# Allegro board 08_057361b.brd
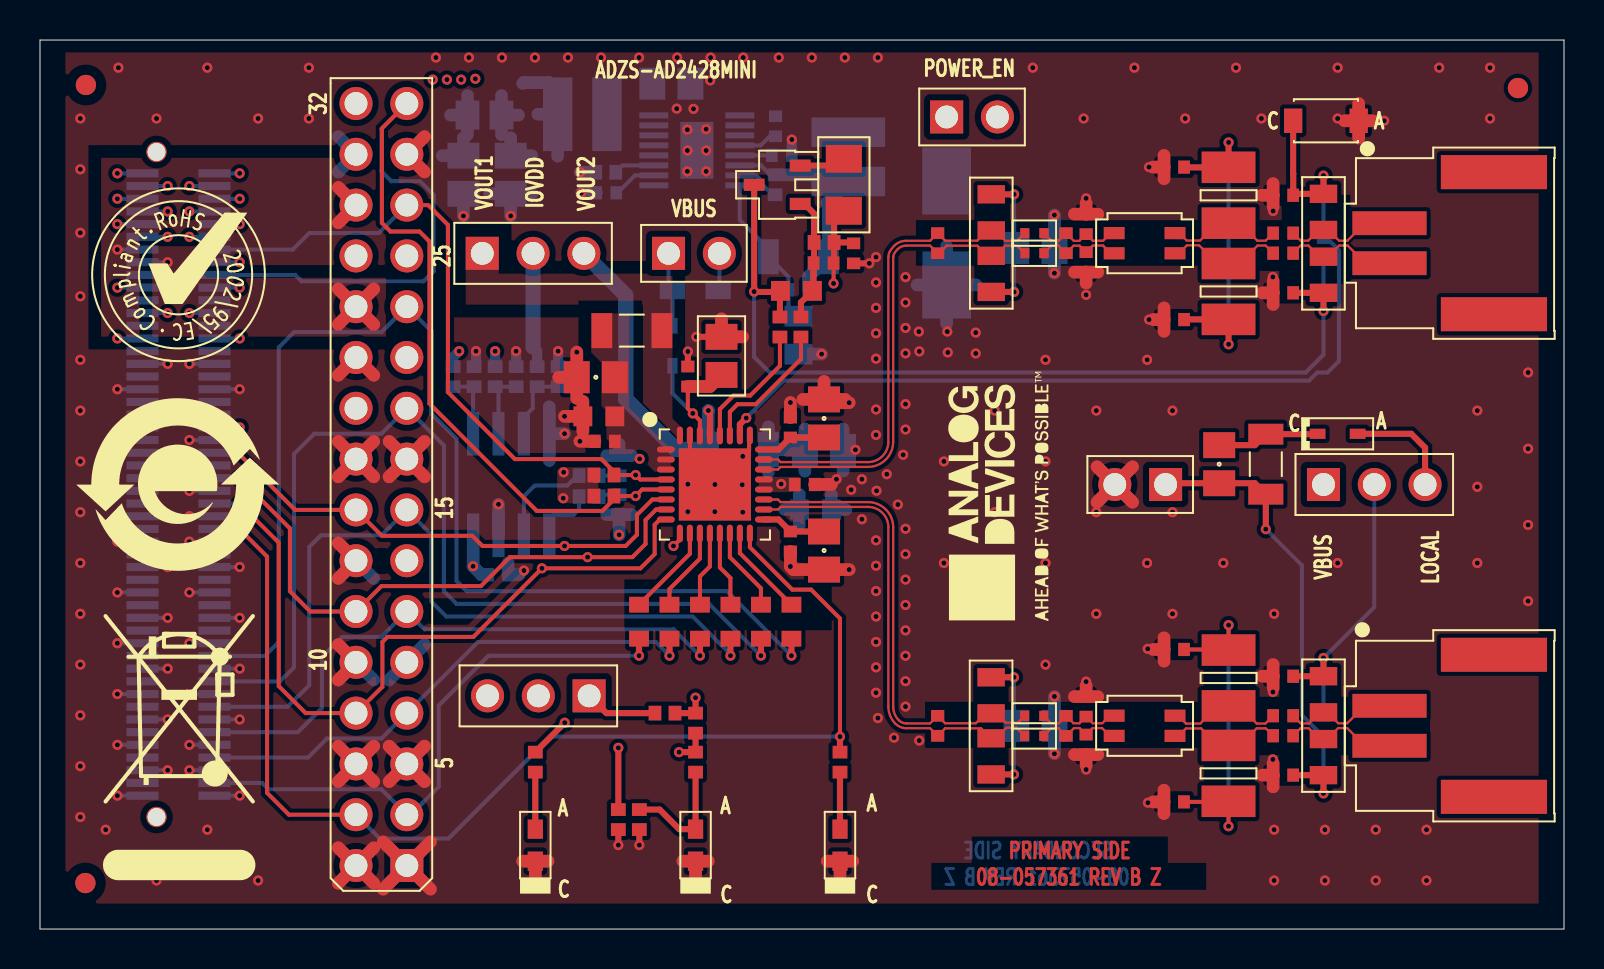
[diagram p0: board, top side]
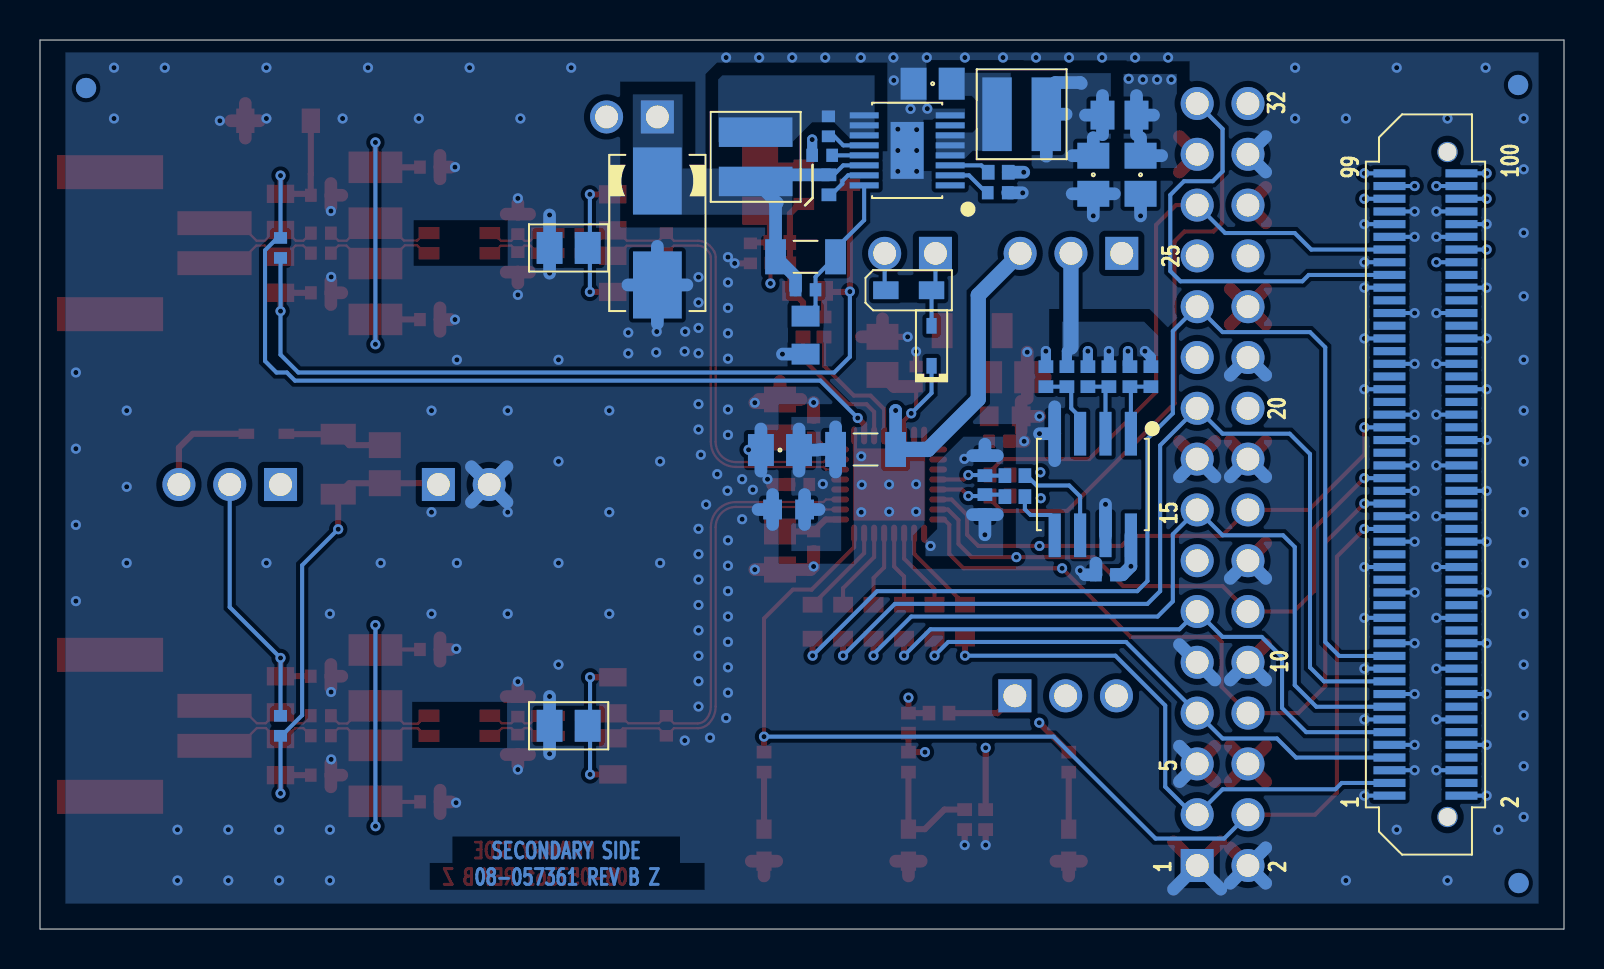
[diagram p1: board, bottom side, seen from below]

Outline 76.2 x 44.45 mm; copper layers: TOP, L2_GND, L3_PWR, BOTTOM. Coordinates in mm from the lower left corner of the outline.
Outline path: 0,44.45 0,0 76.2,0 76.2,44.45 0,44.45

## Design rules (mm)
constraint set DEFAULT: min track width 0.203
net group A: nets AN AP
net group A2: nets UNNAMED_3_CAP_I10_N2 UNNAMED_3_CAP_I12_N2
net group A3: nets UNNAMED_3_CAP_I20_N1 UNNAMED_3_CAP_I22_N1
net group A4: nets UNNAMED_3_CAP_I20_N2 UNNAMED_3_CAP_I22_N2
net group B: nets BN BP

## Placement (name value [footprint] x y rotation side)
C1  4.7UF  [C0805H60]  27.79 27.59 0 top
C2  0.1UF  [C0402]  28.24 24.38 0 top
C3  4700PF  [C0603]  27.94 25.63 0 top
C4  4.7UF  [C0805H60]  39.2 23.95 180 bottom
C5  4700PF  [C0603]  38.77 20.97 180 bottom
C6  0.1UF  [C0402]  32.39 27.62 270 top
C7  0.1UF  [C0402]  37.52 25.07 270 top
C8  0.1UF  [C0402]  37.52 19.38 90 top
C9  0.1UF  [C0402]  38.24 22.23 180 top
C10  10UF  [C0805H53]  34.07 28.66 270 top
C11  4.7UF  [C0805H60]  39.2 25.53 270 top
C12  4.7UF  [C0805H60]  39.2 18.92 90 top
C13  15NF  [C0402]  39.18 33.3 0 top
C14  3300PF  [C0603]  37.82 31.91 180 top
C15  0.033UF  [C0402]  40.68 33.78 90 top
C16  0.33UF  [C0805H53]  49.77 10.16 180 bottom
C17  12PF  [C0402]  44.88 10.16 90 top
C18  27PF  [C0402]  52.31 11.12 90 top
C19  27PF  [C0402]  52.31 9.22 90 top
C20  12PF  [C0402]  51.31 10.16 90 top
C21  0.033UF  [C0402]  56.7 13.98 180 top
C22  0.033UF  [C0402]  56.7 6.36 0 top
C23  0.01UF  [C0402]  62.16 10.66 0 top
C24  0.01UF  [C0402]  62.16 9.66 0 top
C25  0.033UF  [C0402]  62.16 12.64 0 top
C26  0.033UF  [C0402]  62.16 7.69 0 top
C27  0.033UF  [C0402]  64.17 10.16 90 bottom
C28  4.7UF  [C0805H60]  58.96 23.24 90 top
C29  0.33UF  [C0805H53]  49.77 34.05 180 bottom
C30  12PF  [C0402]  44.88 34.29 270 top
C31  27PF  [C0402]  52.31 33.34 270 top
C32  27PF  [C0402]  52.31 35.24 270 top
C33  12PF  [C0402]  51.31 34.29 270 top
C34  0.033UF  [C0402]  56.7 38.09 180 top
C35  0.033UF  [C0402]  56.7 30.47 0 top
C36  0.01UF  [C0402]  62.16 33.79 0 top
C37  0.01UF  [C0402]  62.16 34.79 0 top
C38  0.033UF  [C0402]  62.16 31.81 0 top
C39  0.033UF  [C0402]  62.16 36.69 0 top
C40  0.033UF  [C0402]  64.17 34.05 270 bottom
C41  4.7UF  [C0805H60]  21.17 37.71 90 bottom
C42  4.7UF  [C0805H60]  23.54 37.71 90 bottom
C43  4.7UF  [C0805H60]  31.57 42.27 180 bottom
C44  0.01uF  [C0402]  28.31 36.81 0 bottom
C45  10pF  [C0402]  37.92 31.96 0 bottom
C46  0.1uF  [C0402]  22.9 17.71 0 bottom
C47  0.1uF  [C0402]  36.78 40.13 90 bottom
C48  1uF  [C0402]  37.09 38.68 0 bottom
C49  47UF  [C7343-43]  45.33 34.8 270 bottom
D1  CDBU0130L  [SOD523F]  31.62 29.16 90 bottom
D2  ZLLS400TA  [SOD323]  32.77 31.94 180 bottom
D3  CDBU0130L  [SOD523F]  64.88 24.76 0 top
D4  TPSMF4L28A  [SOD123FL]  64.3 40.41 0 top
DS1  APT1608LVBC/D  [LED0603]  40 4.19 90 top
DS2  APT1608LVBC/D  [LED0603]  24.77 4.19 90 top
DS3  APT1608LVBC/D  [LED0603]  32.78 4.19 90 top
E1  220OHM  [L0805]  22.23 40.69 0 bottom
L1  3.3UH  [L0805H57]  47.55 11.68 270 top
L2  3.3UH  [L0805H57]  47.55 8.63 270 top
L3  180NH  [L0402-3]  49.71 10.66 0 top
L4  180NH  [L0402-3]  49.71 9.66 0 top
L5  100UH  [LSML126W98H98]  55.23 10.16 0 top
L6  3.3UH  [L0805H57]  64.17 11.74 90 top
L7  3.3UH  [L0805H57]  64.17 8.6 90 top
L8  3.3UH  [L0805H57]  47.56 32.76 90 top
L9  3.3UH  [L0805H57]  47.56 35.83 90 top
L10  180NH  [L0402-3]  49.72 33.79 0 top
L11  180NH  [L0402-3]  49.72 34.79 0 top
L12  100UH  [LSML126W98H98]  55.23 34.29 0 top
L13  3.3UH  [L0805H57]  64.17 32.71 270 top
L14  3.3UH  [L0805H57]  64.17 35.85 270 top
L15  4.7uH  [LSMSQ157H83]  27.12 40.74 0 bottom
L16  2.2uH  [LSMSQ157H83]  40.42 38.61 270 bottom
NOREF  -  []  0 44.45 0 top
NOREF#2  -  []  76.2 0 0 top
NOREF#3  -  []  21.18 303 0 top
NOREF#4  -  []  0 44.45 270 top
NOREF#5  -  []  47.95 21.34 90 top
NOREF#6  -  []  -39.78 -67.84 0 top
NOREF#7  -  [unnamed#2]  2.27 2.3 0 top
NOREF#8  -  []  5.83 5.6 0 top
NOREF#9  -  []  16.23 19.33 0 top
NOREF#10  -  []  76.2 44.45 180 top
NOREF#11  -  [unnamed#2]  73.9 42.05 0 top
NOREF#12  -  []  31.12 -36.83 270 top
NOREF#13  -  []  134.54 129.29 0 top
NOREF#14  -  [unnamed#2]  2.29 42.2 0 top
NOREF#15  -  []  -39.78 -67.84 0 top
NOREF#16  -  []  -39.78 -67.84 0 top
NOREF#17  -  []  -1.68 258.55 0 top
NOREF#18  -  []  76.2 0 90 top
NOREF#19  -  []  5.83 5.6 0 top
NOREF#20  -  []  38.54 66.26 0 top
NOREF#21  -  []  0 44.45 0 top
NOREF#22  -  []  6.93 32.71 0 top
NOREF#23  -  []  -29.6 143.68 0 top
NOREF#24  -  []  0 0 0 top
NOREF#25  -  []  0 0 0 top
NOREF#26  -  []  -39.78 -67.84 0 top
NOREF#27  -  []  76.2 0 90 top
NOREF#28  -  []  6.88 22.23 0 top
NOREF#29  -  []  0 0 0 top
NOREF#30  -  [unnamed#2]  2.27 2.3 180 bottom
NOREF#31  -  [unnamed#2]  73.9 42.05 180 bottom
NOREF#32  -  [unnamed#2]  2.29 42.2 180 bottom
P1  LSS-150-01-L-DV-A-K  [CNSAMTECLSS-150-01-X-DV-A]  6.93 22.23 90 bottom
P2  TSW-116-08-G-D  [CNBERG2X16H330LD36]  18.34 3.17 90 top
P3  22-10-2031  [CNHDR1X3H440]  22.11 33.78 0 top
P4  22-10-2031  [CNHDR1X3H440]  27.46 11.66 180 top
P5  3-644456-2  [CNHDR1X2H408]  31.43 33.78 0 top
P6  22-10-2031  [CNHDR1X3H440]  64.17 22.23 0 top
P7  3-644456-2  [CNHDR1X2H408]  56.28 22.23 180 top
P8  3-644456-2  [CNHDR1X2H408]  45.33 40.6 0 top
P9  502352-0200  [CNHDR1X2H260]  70.75 10.16 270 top
P10  502352-0200  [CNHDR1X2H260]  70.75 34.29 270 top
Q1  DMP3098L-7  [SOT23_B]  36.86 37.21 90 top
R1  1.5K  [R0402]  40 8.34 90 top
R2  1.5K  [R0402]  24.77 8.34 90 top
R3  10K  [R0402]  32.78 10.29 90 top
R4  1.5K  [R0402]  32.78 8.34 90 top
R5  10K  [R0402]  29.97 5.47 90 top
R6  33  [R0603]  29.95 15.37 90 top
R7  33  [R0603]  31.47 15.37 90 top
R8  33  [R0603]  33 15.37 90 top
R9  33  [R0603]  34.52 15.37 90 top
R10  33  [R0603]  36.05 15.37 90 top
R11  33  [R0603]  37.57 15.37 90 top
R12  10K  [R0402]  31.25 10.79 0 top
R13  10K  [R0402]  28.92 5.47 90 top
R14  10K  [R0402]  28.2 22.7 180 top
R15  10K  [R0402]  28.2 21.65 180 top
R16  0  [R1206]  29.59 29.92 180 top
R17  0  [R1206]  34.92 23.98 0 bottom
R18  3.3K  [R0402]  38.05 30.1 90 top
R19  1K  [R0402]  37 30.1 90 top
R20  33K  [R0402]  39.2 34.33 0 top
R21  1  [R1206-2]  40.19 37.21 270 top
R22  120  [R1210]  59.43 12.55 270 top
R23  120  [R1210]  59.42 7.78 270 top
R24  4.7K  [R1206]  61.29 23.24 90 top
R25  120  [R1210]  59.43 31.88 90 top
R26  120  [R1210]  59.43 36.69 90 top
R27  10K  [R0402]  20.66 27.62 90 bottom
R28  10K  [R0402]  21.71 27.62 270 bottom
R29  10K  [R0402]  22.76 27.62 90 bottom
R30  10K  [R0402]  23.81 27.62 270 bottom
R31  10K  [R0402]  24.86 27.62 90 bottom
R32  10K  [R0402]  25.91 27.62 270 bottom
R33  18.2K  [R0402]  28.29 37.84 0 bottom
R34  130K  [R0805]  37.92 29.69 90 bottom
R35  1MEG  [R1206]  37.92 33.61 0 bottom
R36  100K  [R0402]  36.75 37.21 270 bottom
R37  0  [R0402]  27.46 21.62 0 bottom
R38  0  [R0402]  27.46 22.67 0 bottom
R39  3.3K  [R0402]  28.96 21.22 270 bottom
R40  3.3K  [R0402]  28.96 23.17 90 bottom
U1  AD2428WCCSZ  [QFN32_5X5_PAD3_6X3_6]  33.74 22.23 270 top
U2  24AA512T-I/SN  [SO8]  23.56 22.23 0 bottom
U3  LT8620EMSE#PBF  [MSOP16_PAD2_845X1_651]  32.84 38.93 90 bottom

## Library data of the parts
C1 C4 C11 C12 = CAP: Tolerance: 10; User Part Number: UPN; alternate symbols: (); part number: CAP_SM-4.7UF,35V,10,E030887,C0805H60; tolerance: 10
C2 C6-C9 = CAP: User Part Number: UPN; Tolerance: 10; alternate symbols: (); part number: CAP_SM-0.1UF,25V,10,E033331,C0402; tolerance: 10
C3 C5 = CAP: User Part Number: UPN; Tolerance: 5; alternate symbols: (); part number: CAP_SM-4700PF,50V,5,E029760,C0603; tolerance: 5
C10 = CAP: Tolerance: 10; User Part Number: UPN; alternate symbols: (C0805SP); part number: CAP_SM-10UF,6.3V,10,E028139,C0805H53; tolerance: 10
C13 = CAP: User Part Number: UPN; Tolerance: 10; alternate symbols: (); part number: CAP_SM-15NF,35V,10,E033385,C0402; tolerance: 10
C14 = CAP: User Part Number: UPN; Tolerance: 10; alternate symbols: (); part number: CAP_SM-3300PF,50V,10,E030855,C0603; tolerance: 10
C15 C21 C22 C25-C27 C34 C35 C38-C40 = CAP: User Part Number: UPN; Tolerance: 10; alternate symbols: (); part number: CAP_SM-0.033UF,25V,10,E025701,C0402; tolerance: 10
C16 C29 = CAP: Tolerance: 10; User Part Number: UPN; alternate symbols: (); part number: CAP_SM-0.33UF,25V,10,E031755,C0805H53; tolerance: 10
C17 C20 C30 C33 = CAP: User Part Number: UPN; Tolerance: 5; alternate symbols: (); part number: CAP_SM-12PF,50V,5,E034633,C0402; tolerance: 5
C18 C19 C31 C32 = CAP: User Part Number: UPN; Tolerance: 5; alternate symbols: (); part number: CAP_SM-27PF,50V,5,E033384,C0402; tolerance: 5
C23 C24 C36 C37 = CAP: User Part Number: UPN; Tolerance: 10; alternate symbols: (); part number: CAP_SM-0.01UF,25V,10,E030894,C0402; tolerance: 10
C28 C41-C43 = CAP: Tolerance: 10; User Part Number: UPN; alternate symbols: (); part number: CAP_SM-4.7UF,35V,10,E026260,C0805H60; tolerance: 10
C44 = CAP: User Part Number: UPN; Tolerance: -20 to 80%; alternate symbols: (); part number: CAP_SM-0.01UF,50V,-20 TO 80%,E012614,C0402; tolerance: -20 to 80%
C45 = CAP: User Part Number: UPN; Tolerance: 5; alternate symbols: (); part number: CAP_SM-10PF,50V,5,E007982,C0402; tolerance: 5
C46 C47 = CAP: User Part Number: UPN; Tolerance: 10; alternate symbols: (); part number: CAP_SM-0.1UF,35V,10,E019488,C0402; tolerance: 10
C48 = CAP: User Part Number: UPN; Tolerance: 20; alternate symbols: (); part number: CAP_SM-1UF,16V,20,E020695,C0402; tolerance: 20
C49 = CAPP: Tolerance: 10; User Part Number: UPN; alternate symbols: (); part number: CAPP_SM-47UF,35V,10,E024417,C7343-43; tolerance: 10
D1 D3 = DIOSCHOTTKY: Tolerance: N/A; User Part Number: UPN; alternate symbols: (); part number: DIOSCHOTTKY_SM-CDBU0130L,35V,N/A,E019837,SOD523F; tolerance: N/A
D2 = DIOSCHOTTKY: Tolerance: N/A; User Part Number: UPN; alternate symbols: (); part number: DIOSCHOTTKY_SM-ZLLS400TA,40V,N/A,E032795,SOD323; tolerance: N/A
D4 = DIOZNR: User Part Number: UPN; Tolerance: N/A; alternate symbols: (); part number: DIOZNR_SM-TPSMF4L28A,28V,N/A,E033310,SOD123FL; tolerance: N/A
DS1-DS3 = DIOLED: Tolerance: N/A; User Part Number: UPN; alternate symbols: (); part number: DIOLED_SM-APT1608LVBC/D,2.65V,N/A,E039384,LED0603; tolerance: N/A
E1 = FERRITE: User Part Number: UPN; Tolerance: 25; alternate symbols: (); part number: FERRITE_SM-220OHM,25,E017491,L0805; tolerance: 25
L1 L2 L6-L9 L13 L14 = IND: User Part Number: UPN; Tolerance: 20; alternate symbols: (); part number: IND_SM-3.3UH,20,E033480,L0805H57; tolerance: 20
L3 L4 L10 L11 = IND: Tolerance: 5; User Part Number: UPN; alternate symbols: (); part number: IND_SM-180NH,5,E034614,L0402-3; tolerance: 5
L5 L12 = CHOKE4P_V7: Tolerance: +50/-30; User Part Number: UPN; alternate symbols: (); part number: CHOKE4P_V7_SM-100UH,+50/-30,E034437,LSML126W98H98; tolerance: +50/-30
L15 = IND: User Part Number: UPN; Tolerance: 20; alternate symbols: (); part number: IND_SM-4.7UH,20,E014920,LSMSQ157H83; tolerance: 20
L16 = IND: User Part Number: UPN; Tolerance: 20; alternate symbols: (); part number: IND_SM-2.2UH,20,E016651,LSMSQ157H83; tolerance: 20
P1 = CN100P_V2: Tolerance: N/A; User Part Number: UPN; alternate symbols: (); part number: CN100P_V2_SM-LSS-150-01-L-DV-A-K,E035696,CNSAMTECLSS-150-01-X-DV-A; tolerance: N/A
P2 = CN32P: Tolerance: N/A; User Part Number: UPN; alternate symbols: (); part number: CN32P_TH-TSW-116-08-G-D,E000802,CNBERG2X16H330LD36; tolerance: N/A
P3 P4 P6 = CN3P: Tolerance: N/A; User Part Number: UPN; alternate symbols: (); part number: CN3P_TH-22-10-2031,E019068,CNHDR1X3H440; tolerance: N/A
P5 P7 P8 = CN2P: User Part Number: UPN; Tolerance: N/A; alternate symbols: (); part number: CN2P_TH-3-644456-2,E024442,CNHDR1X2H408; tolerance: N/A
P9 P10 = CN2P_2PAD: Tolerance: N/A; User Part Number: UPN; alternate symbols: (); part number: CN2P_2PAD_SM-502352-0200,E019047,CNHDR1X2H260; tolerance: N/A
Q1 = TRANPMOSFET_V12: User Part Number: UPN; Tolerance: N/A; alternate symbols: (); part number: TRANPMOSFET_V12_SM-DMP3098L-7,E033355,SOT23_B; tolerance: N/A
R1 R2 R4 = RES: User Part Number: UPN; Tolerance: 1; alternate symbols: (R0402L); part number: RES_SM-1.5K,E003782,1/16W,1,R0402; tolerance: 1
R3 R5 R12-R15 R27-R32 = RES: User Part Number: UPN; Tolerance: 1; alternate symbols: (); part number: RES_SM-10K,E031669,1/16W,1,R0402; tolerance: 1
R6-R11 = RES: User Part Number: UPN; Tolerance: 5; alternate symbols: (R0603L); part number: RES_SM-33,E026149,1/10W,5,R0603; tolerance: 5
R16 R17 = RES: User Part Number: UPN; Tolerance: N/A; alternate symbols: (); part number: RES_SM-0,E031926,1/4W,N/A,R1206; tolerance: N/A
R18 R39 R40 = RES: User Part Number: UPN; Tolerance: 1; alternate symbols: (R0402L,R0402L_ALT); part number: RES_SM-3.3K,E010034,1/10W,1,R0402; tolerance: 1
R19 = RES: User Part Number: UPN; Tolerance: 1; alternate symbols: (R0402L); part number: RES_SM-1K,E025035,1/5W,1,R0402; tolerance: 1
R20 = RES: User Part Number: UPN; Tolerance: 1; alternate symbols: (R0402L); part number: RES_SM-33K,E021200,1/16W,1,R0402; tolerance: 1
R21 = RES: User Part Number: UPN; alternate symbols: (); part number: RES_SM-1,E031048,3/4W,1,R1206-2
R22 R23 R25 R26 = RES: Tolerance: 1; User Part Number: UPN; alternate symbols: (); part number: RES_SM-120,E033377,3/4W,1,R1210; tolerance: 1
R24 = RES: User Part Number: UPN; Tolerance: 1; alternate symbols: (); part number: RES_SM-4.7K,E030745,1/2W,1,R1206; tolerance: 1
R33 = RES: User Part Number: UPN; Tolerance: 1; alternate symbols: (R0402L); part number: RES_SM-18.2K,E010424,1/16W,1,R0402; tolerance: 1
R34 = RES: User Part Number: UPN; Tolerance: 1; alternate symbols: (R0805L); part number: RES_SM-130K,E003566,1/8W,1,R0805; tolerance: 1
R35 = RES: User Part Number: UPN; Tolerance: 1; alternate symbols: (); part number: RES_SM-1MEG,E004098,1/4W,1,R1206; tolerance: 1
R36 = RES: User Part Number: UPN; Tolerance: 5; alternate symbols: (R0402L); part number: RES_SM-100K,E003464,1/10W,5,R0402; tolerance: 5
R37 R38 = RES: User Part Number: UPN; Tolerance: 1; alternate symbols: (R0402L); part number: RES_SM-0,E010661,1/16W,1,R0402; tolerance: 1
U1 = AD242X_V2: Tolerance: N/A; User Part Number: UPN; alternate symbols: (); part number: AD242X_V2_SM-AD2428WCCSZ,E033309,QFN32_5X5_PAD3_6X3_6; tolerance: N/A
U2 = IC24XX512: Tolerance: N/A; User Part Number: UPN; alternate symbols: (); part number: IC24XX512_SM-24AA512T-I/SN,E035973,SO8; tolerance: N/A
U3 = LINLT8620: Tolerance: N/A; User Part Number: UPN; alternate symbols: (); part number: LINLT8620_SM-LT8620EMSE#PBF,E032165,MSOP16_PAD2_845X1_651; tolerance: N/A

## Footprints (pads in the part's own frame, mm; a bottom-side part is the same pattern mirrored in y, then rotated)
C0402
  rect 0.584x0.66 smd: 1(-0.5,0) 2(0.5,0)
C0603
  rect 0.94x0.991 smd: 1(-0.8,0) 2(0.8,0)
C0805H53
  rect 1.295x1.6 smd: 1(-0.953,0) 2(0.953,0)
C0805H60
  rect 1.295x1.6 smd: 1(-0.953,0) 2(0.953,0)
C7343-43
  rect 3.353x2.438 smd: N(2.6,0) P(-2.6,0)
CNBERG2X16H330LD36
  rect 1.651x1.651 hole 1.143: 1(0,0)
  round 1.651 hole 1.143: 2(0,2.54) 3(2.54,0) 4(2.54,2.54) 5(5.08,0) 6(5.08,2.54) 7(7.62,0) 8(7.62,2.54) 9(10.16,0) 10(10.16,2.54) 11(12.7,0) 12(12.7,2.54) 13(15.24,0) 14(15.24,2.54) 15(17.78,0) 16(17.78,2.54) 17(20.32,0) 18(20.32,2.54) 19(22.86,0) 20(22.86,2.54) 21(25.4,0) 22(25.4,2.54) 23(27.94,0) 24(27.94,2.54) 25(30.48,0) 26(30.48,2.54) 27(33.02,0) 28(33.02,2.54) 29(35.56,0) 30(35.56,2.54) 31(38.1,0) 32(38.1,2.54)
CNHDR1X2H260
  rect 1.194x3.708 smd: 1(-1,-3.276) 2(1,-3.276)
  rect 1.702x5.309 smd: PAD1(-3.551,1.946) PAD2(3.551,1.946)
CNHDR1X2H408
  rect 1.651x1.651 hole 1.143: 1(0,0)
  round 1.651 hole 1.143: 2(2.54,0)
CNHDR1X3H440
  rect 1.651x1.651 hole 1.143: 1(0,0)
  round 1.651 hole 1.143: 2(2.54,0) 3(5.08,0)
CNSAMTECLSS-150-01-X-DV-A
  round 1.016 hole 0.889 unplated: (-16.625,-1.1) (16.625,-1.1)
  rect 0.406x1.6 smd: 1(-15.557,1.8) 2(-15.557,-1.8) 3(-14.922,1.8) 4(-14.922,-1.8) 5(-14.287,1.8) 6(-14.287,-1.8) 7(-13.652,1.8) 8(-13.652,-1.8) 9(-13.018,1.8) 10(-13.018,-1.8) 11(-12.383,1.8) 12(-12.383,-1.8) 13(-11.748,1.8) 14(-11.748,-1.8) 15(-11.113,1.8) 16(-11.113,-1.8) 17(-10.477,1.8) 18(-10.477,-1.8) 19(-9.842,1.8) 20(-9.842,-1.8) 21(-9.207,1.8) 22(-9.207,-1.8) 23(-8.572,1.8) 24(-8.572,-1.8) 25(-7.938,1.8) 26(-7.938,-1.8) 27(-7.303,1.8) 28(-7.303,-1.8) 29(-6.668,1.8) 30(-6.668,-1.8) 31(-6.032,1.8) 32(-6.032,-1.8) 33(-5.397,1.8) 34(-5.397,-1.8) 35(-4.763,1.8) 36(-4.763,-1.8) 37(-4.128,1.8) 38(-4.128,-1.8) 39(-3.493,1.8) 40(-3.493,-1.8) 41(-2.857,1.8) 42(-2.857,-1.8) 43(-2.223,1.8) 44(-2.223,-1.8) 45(-1.587,1.8) 46(-1.587,-1.8) 47(-0.953,1.8) 48(-0.953,-1.8) 49(-0.318,1.8) 50(-0.318,-1.8) 51(0.318,1.8) 52(0.318,-1.8) 53(0.953,1.8) 54(0.953,-1.8) 55(1.587,1.8) 56(1.587,-1.8) 57(2.223,1.8) 58(2.223,-1.8) 59(2.857,1.8) 60(2.857,-1.8) 61(3.493,1.8) 62(3.493,-1.8) 63(4.128,1.8) 64(4.128,-1.8) 65(4.763,1.8) 66(4.763,-1.8) 67(5.397,1.8) 68(5.397,-1.8) 69(6.032,1.8) 70(6.032,-1.8) 71(6.668,1.8) 72(6.668,-1.8) 73(7.303,1.8) 74(7.303,-1.8) 75(7.938,1.8) 76(7.938,-1.8) 77(8.572,1.8) 78(8.572,-1.8) 79(9.207,1.8) 80(9.207,-1.8) 81(9.842,1.8) 82(9.842,-1.8) 83(10.477,1.8) 84(10.477,-1.8) 85(11.113,1.8) 86(11.113,-1.8) 87(11.748,1.8) 88(11.748,-1.8) 89(12.383,1.8) 90(12.383,-1.8) 91(13.018,1.8) 92(13.018,-1.8) 93(13.652,1.8) 94(13.652,-1.8) 95(14.287,1.8) 96(14.287,-1.8) 97(14.922,1.8) 98(14.922,-1.8) 99(15.557,1.8) 100(15.557,-1.8)
L0402-3
  rect 0.457x0.508 smd: 1(-0.479,0) 2(0.479,0)
L0805
  rect 1.194x1.448 smd: 1(-0.85,0) 2(0.85,0)
L0805H57
  rect 0.914x1.372 smd: 1(-0.902,0) 2(0.902,0)
LED0603
  rect 0.965x0.762 smd: A(0.8,0) C(-0.8,0)
LSML126W98H98
  rect 1.041x0.61 smd: 1(-1.521,0.505) 2(-1.521,-0.505) 3(1.521,-0.505) 4(1.521,0.505)
LSMSQ157H83
  rect 1.473x3.683 smd: 1(-1.232,0) 2(1.232,0)
MSOP16_PAD2_845X1_651
  rect 0.305x1.448 smd: 1(-1.75,-2.15) 2(-1.25,-2.15) 3(-0.75,-2.15) 4(-0.25,-2.15) 5(0.25,-2.15) 6(0.75,-2.15) 7(1.25,-2.15) 8(1.75,-2.15) 9(1.75,2.15) 10(1.25,2.15) 11(0.75,2.15) 12(0.25,2.15) 13(-0.25,2.15) 14(-0.75,2.15) 15(-1.25,2.15) 16(-1.75,2.15)
  rect 2.845x1.651 smd: PAD(0,0)
QFN32_5X5_PAD3_6X3_6
  oval 0.305x0.889 smd: 1(-1.75,-2.451) 2(-1.25,-2.451) 3(-0.75,-2.451) 4(-0.25,-2.451) 5(0.25,-2.451) 6(0.75,-2.451) 7(1.25,-2.451) 8(1.75,-2.451) 17(1.75,2.451) 18(1.25,2.451) 19(0.75,2.451) 20(0.25,2.451) 21(-0.25,2.451) 22(-0.75,2.451) 23(-1.25,2.451) 24(-1.75,2.451)
  oval 0.889x0.305 smd: 9(2.451,-1.75) 10(2.451,-1.25) 11(2.451,-0.75) 12(2.451,-0.25) 13(2.451,0.25) 14(2.451,0.75) 15(2.451,1.25) 16(2.451,1.75) 25(-2.451,1.75) 26(-2.451,1.25) 27(-2.451,0.75) 28(-2.451,0.25) 29(-2.451,-0.25) 30(-2.451,-0.75) 31(-2.451,-1.25) 32(-2.451,-1.75)
  rect 3.607x3.607 smd: PAD(0,0)
R0402
  rect 0.635x0.737 smd: 1(-0.5,0) 2(0.5,0)
R0603
  rect 0.787x0.991 smd: 1(-0.85,0) 2(0.85,0)
R0805
  rect 1.041x1.397 smd: 1(-0.95,0) 2(0.95,0)
R1206
  rect 1.041x1.753 smd: 1(-1.5,0) 2(1.5,0)
R1206-2
  rect 1.397x1.803 smd: 1(-1.298,0) 2(1.298,0)
R1210
  rect 1.575x2.692 smd: 1(-1.397,0) 2(1.397,0)
SO8
  rect 0.61x2.184 smd: 1(-1.905,-2.54) 2(-0.635,-2.54) 3(0.635,-2.54) 4(1.905,-2.54) 5(1.905,2.54) 6(0.635,2.54) 7(-0.635,2.54) 8(-1.905,2.54)
SOD123FL
  rect 0.914x1.219 smd: A(1.638,0) C(-1.638,0)
SOD323
  rect 1.27x0.889 smd: A(1.143,0) C(-1.143,0)
SOD523F
  rect 0.787x0.508 smd: A(1,0) C(-1,0)
SOT23_B
  rect 0.61x1.041 smd: 1(-0.958,-1.15) 2(0.958,-1.15) 3(0,1.15)
unnamed#2
  round 1.016 smd: (0,0)

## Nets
DGND: C1.1 C2.1 C3.1 C4.1 C5.1 C6.1 C7.1 C8.1 C9.1 C10.1 C11.1 C12.1 C15.1 C16.1 C18.2(N2) C19.1 C21.2(N2) C22.1 C25.1 C26.1 C29.1 C31.2(N2) C32.1 C34.2(N2) C35.1 C38.1 C39.1 C41.1 C42.1 C43.1 C44.1 C46.2(N2) C48.2(N2) C49.N(N2) D4.A(P) DS1.C DS2.C DS3.C P1.1 P1.2 P1.5 P1.6 P1.9 P1.10 P1.13 P1.14 P1.17 P1.18(N9) P1.21 P1.22 P1.25 P1.26 P1.29 P1.30 P1.33 P1.34 P1.37 P1.38 P1.41 P1.42 P1.45 P1.46 P1.49 P1.50 P1.53 P1.54 P1.57 P1.58 P1.61 P1.62 P1.65 P1.66 P1.69 P1.70 P1.73 P1.74 P1.77 P1.78 P1.81 P1.82 P1.85 P1.89 P1.90 P1.91 P1.92 P1.93 P1.94 P2.1 P2.2 P2.5 P2.6 P2.9(N9) P2.10 P2.13 P2.14 P2.17 P2.18 P2.21 P2.22 P2.25 P2.26 P2.29 P2.30 P7.2(N2) R5.1 R13.1 R28.1 R30.1 R32.1 R33.1 R34.1 U1.25 U1.31 U1.PAD(VSS_3) U2.4 U2.7(WP) U3.8 U3.PAD
VBAT_IN: C41.2(N2) E1.1 P1.96 P1.98 P1.100 P2.32
VSSN: C39.2(N2) C40.1 D4.C L14.1 U1.26
A2B_VBUS: D1.A(P) D2.A(P) P1.95 P1.97 P1.99 P2.20 P5.1 P6.1 P8.2(N2)
ACM: C8.2(N2) C12.2(N2) U1.17
ADR1/IO1: P1.51 P2.12 R3.1 R4.2(N2) U1.7
ADR2/IO2: P1.47 P2.8 P4.2 U1.8
AN: C17.1 L2.1 L4.1 U1.18
AP: C17.2(N2) L1.2(N2) L3.1 U1.19
BCM: C7.2(N2) C11.2(N2) U1.24
BLCK: P1.3 P2.3 R6.1
BN: C30.1 L9.1 L11.1 U1.23
BP: C30.2(N2) L8.2(N2) L10.1 U1.22
DRX0: P1.19 P2.19 R10.1
DRX1: P1.23 P2.23 R11.1
DTX0: P1.11 P2.11 R8.1
DTX1: P1.15 P2.15 R9.1
IO7: P1.43 P2.4 R1.2(N2) U1.16
IOVDD: C46.1 P3.2 R3.2(N2) R12.2(N2) R14.2(N2) R15.2(N2) R27.2(N2) R29.2(N2) R31.2(N2) R39.2(N2) R40.2(N2) U1.9 U2.8
IRQ: P1.59 P2.16 R2.2(N2) U1.6
SCL: P1.87 P2.27 R14.1 R38.2(N2) R40.1 U1.4
SDA: P1.83 P2.31 R15.1 R37.2(N2) R39.1 U1.5
SENSE: C14.2(N2) C38.2(N2) C40.2(N2) L13.2(N2) Q1.3 R19.2(N2)
SYNC: P1.7 P2.7 R7.1
UNNAMED_2_AD242XV2_I1_ATRXVDD: C4.2(N2) C5.2(N2) C9.2(N2) R17.2(N2) U1.20 U1.21
UNNAMED_2_AD242XV2_I1_BCLK: R6.2(N2) U1.10
UNNAMED_2_AD242XV2_I1_DRX0: R10.2(N2) U1.14
UNNAMED_2_AD242XV2_I1_DRX1: R11.2(N2) U1.15
UNNAMED_2_AD242XV2_I1_DTX0: R8.2(N2) U1.12
UNNAMED_2_AD242XV2_I1_DTX1: R9.2(N2) U1.13
UNNAMED_2_AD242XV2_I1_DVDD1: C1.2(N2) C2.2(N2) C3.2(N2) R16.2(N2) U1.1 U1.2 U1.3
UNNAMED_2_AD242XV2_I1_SENSE: R19.1 U1.28
UNNAMED_2_AD242XV2_I1_SWP: R18.1 U1.27
UNNAMED_2_AD242XV2_I1_SYNC: R7.2(N2) U1.11
UNNAMED_2_AD242XV2_I1_VIN: C6.2(N2) C10.2(N2) D1.C U1.30
UNNAMED_2_CAP_I30_N1: C13.1 C14.1 Q1.1 R18.2(N2) R20.1
UNNAMED_2_CAP_I34_N2: C13.2(N2) C15.2(N2) D2.C P5.2(N2) R20.2(N2) R21.2(N2)
UNNAMED_2_CN3P_I84_N1: P4.1 R12.1
UNNAMED_2_CN3P_I84_N3: P4.3(N3) R13.2(N2)
UNNAMED_2_DIOLED_I85_P: DS1.A(P) R1.1
UNNAMED_2_DIOLED_I86_P: DS2.A(P) R2.1
UNNAMED_2_DIOLED_I87_P: DS3.A(P) R4.1 R5.2(N2)
UNNAMED_2_RES_I39_N1: Q1.2(S) R21.1
UNNAMED_3_CAP_I3_N2: C16.2(N2) L1.1 L2.2(N2)
UNNAMED_3_CAP_I10_N2: C19.2(N2) C20.1 L4.2(N2) L5.2
UNNAMED_3_CAP_I12_N2: C18.1 C20.2(N2) L3.2(N2) L5.1
UNNAMED_3_CAP_I20_N1: C24.1 L5.3 R23.1
UNNAMED_3_CAP_I20_N2: C24.2(N2) L7.2(N2) P9.2
UNNAMED_3_CAP_I22_N1: C23.1 L5.4(N4) R22.2(N2)
UNNAMED_3_CAP_I22_N2: C23.2(N2) L6.1 P9.1
UNNAMED_3_CAP_I24_N2: C26.2(N2) C27.1 C28.1 L7.1 P7.1 R24.1
UNNAMED_3_CAP_I25_N2: C25.2(N2) C27.2(N2) L6.2(N2) P6.2
UNNAMED_3_CAP_I29_N2: C21.1 C22.2(N2) R22.1 R23.2(N2)
UNNAMED_3_CAP_I35_N2: C28.2(N2) D3.C R24.2(N2)
UNNAMED_3_CN3P_I36_N3: D3.A(P) P6.3(N3)
UNNAMED_4_CAP_I5_N1: C36.1 L12.3 R25.2(N2)
UNNAMED_4_CAP_I5_N2: C36.2(N2) L13.1 P10.2
UNNAMED_4_CAP_I9_N1: C37.1 L12.4(N4) R26.1
UNNAMED_4_CAP_I9_N2: C37.2(N2) L14.2(N2) P10.1
UNNAMED_4_CAP_I12_N1: C32.2(N2) C33.1 L11.2(N2) L12.1
UNNAMED_4_CAP_I12_N2: C31.1 C33.2(N2) L10.2(N2) L12.2
UNNAMED_4_IND_I17_N1: C29.2(N2) L8.1 L9.2(N2)
UNNAMED_4_RES_I10_N1: C34.1 C35.2(N2) R25.1 R26.2(N2)
UNNAMED_5_CAP_I9_N2: C43.2(N2) L15.2(N2) U3.4 U3.5 U3.6(VIN_2)
UNNAMED_5_CAP_I12_N2: C44.2(N2) U3.2
UNNAMED_5_CAP_I13_N1: C48.1 U3.13
UNNAMED_5_CAP_I14_N1: C47.1 U3.12
UNNAMED_5_CAP_I14_N2: C47.2(N2) L16.1 U3.9 U3.10 U3.11
UNNAMED_5_CAP_I23_N1: C45.1 R34.2(N2) R35.1 U3.16
UNNAMED_5_CAP_I23_N2: C45.2(N2) C49.P L16.2(N2) P8.1 R35.2(N2) R36.1 U3.14
UNNAMED_5_CAP_I42_N2: C42.2(N2) E1.2(N2) L15.1
UNNAMED_5_IC24XX512_I49_A0: R27.1 R28.2(N2) U2.1
UNNAMED_5_IC24XX512_I49_A1: R29.1 R30.2(N2) U2.2
UNNAMED_5_IC24XX512_I49_A2: R31.1 R32.2(N2) U2.3
UNNAMED_5_IC24XX512_I49_SCL: R38.1 U2.6
UNNAMED_5_IC24XX512_I49_SDA: R37.1 U2.5
UNNAMED_5_LINLT8620_I8_PG: R36.2(N2) U3.15
UNNAMED_5_LINLT8620_I8_RT: R33.2(N2) U3.3
VOUT1: P1.86 P2.24 P3.1 R16.1 U1.32
VOUT2: P1.88 P2.28 P3.3(N3) R17.1 U1.29

Pads without a net: P1 4 8 12 16 20 24 27 28 31 32 35 36 39 40 44 48 52 55 56 60 63 64 67 68 71 72 75 76 79 80 84; P9 PAD1 PAD2; P10 PAD1 PAD2; U3 1 7

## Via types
v1: diameter 0.508, hole 0.254, TOP to BOTTOM, 295 vias

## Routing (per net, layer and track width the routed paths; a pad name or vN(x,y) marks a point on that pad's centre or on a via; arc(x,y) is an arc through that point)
DGND: length 317.9
  TOP w0.203: U1.31 32.49,23.47 v1(33.74,22.23) 35.45,23.93 35.45,24.64 U1.25 ; C11.1 39.37,26.31
  TOP w0.305: C15.1 v1(41.47,33.28) ; v1(32.39,28.87) C6.1 ; R5.1 v1(29.97,4.2) ; R13.1 v1(28.92,4.2) ; C10.1 v1(32.82,29.61)
  TOP w0.635: 52.31,32.3 C31.2 ; C31.2 51.72,32.84 ; C31.2 52.89,32.84 ; C2.1 v1(26.99,24.38) ; P2.17 19.23,24.38 ; P2.17 17.45,22.61 ; P2.17 17.45,24.38 ; P2.17 19.23,22.61 ; 61.11,36.69 C39.1 ; C39.1 61.66,36.1 ; C39.1 61.66,37.27 ; 26.84,26.53 C1.1 ; C1.1 25.94,27.59 ; C1.1 v1(26.84,28.84) ; 51.72,35.74 C32.1 ; C32.1 52.31,36.29 ; C32.1 52.89,35.74 ; C18.2 52.89,11.62 ; C18.2 52.31,12.17 ; C18.2 51.72,11.62 ; 56.2,29.89 C35.1 ; C35.1 56.2,31.06 ; C35.1 55.65,30.47 ; 32.78,2.66 DS3.C ; DS3.C 32.14,3.39 ; DS3.C 33.41,3.39 ; C21.2 56.2,14.56 ; C21.2 56.2,13.39 ; C21.2 55.65,13.98 ; 14.91,19.3 P2.14 14.91,17.53 ; 61.11,7.69 C26.1 ; C26.1 61.66,7.11 ; C26.1 61.66,8.28 ; P2.18 16.69,22.61 ; P2.18 14.91,22.61 ; P2.18 16.69,24.38 ; P2.18 14.91,24.38 ; DS2.C 25.4,3.39 ; DS2.C 24.77,2.66 ; DS2.C 24.13,3.39 ; 52.85,23.11 P7.2 ; P7.2 54.63,21.34 ; P7.2 54.63,23.11 ; P7.2 52.85,21.34 ; 17.45,7.37 P2.5 ; P2.5 19.23,7.37 ; P2.5 19.23,9.14 ; P2.5 17.45,9.14 ; 61.66,31.22 C38.1 ; C38.1 61.11,31.81 ; C38.1 61.66,32.39 ; P2.2 16.69,4.06 ; P2.2 16.69,2.29 ; P2.2 14.91,2.29 ; P2.2 14.91,4.06 ; 56.2,5.77 C22.1 ; C22.1 55.65,6.36 ; C22.1 56.2,6.94 ; 19.23,39.62 P2.29 19.23,37.85 ; P2.1 19.52,4.36 ; P2.1 19.52,1.99 ; P2.1 17.16,1.99 ; P2.1 17.16,4.36 ; C11.1 39.2,27.38 ; C11.1 40.26,26.48 ; C11.1 38.15,26.48 ; 40,2.66 DS1.C ; DS1.C 40.63,3.39 ; DS1.C 39.36,3.39 ; 27.14,24.88 C3.1 ; C3.1 v1(26.23,25.63) ; C3.1 27.14,26.38 ; C8.1 v1(37.52,18.13) 37.68,17.97 C12.1 v1(40.46,17.97) ; 52.31,8.17 C19.1 ; C19.1 51.72,8.72 ; C19.1 52.89,8.72 ; P2.6 16.69,7.37 ; P2.6 16.69,9.14 ; P2.6 14.91,9.14 ; P2.6 14.91,7.37 ; 65.22,40.41 D4.A ; D4.A 65.93,39.55 ; D4.A 65.93,41.28 ; D4.A 66.65,40.41 ; 14.91,27.69 P2.22 16.69,27.69 ; 55.65,38.09 C34.2 ; C34.2 56.2,37.51 ; C34.2 56.2,38.68 ; 14.91,14.22 P2.10 14.91,12.45 ; 34.07,30.51 C10.1 35.13,29.61 ; 61.66,12.05 C25.1 ; C25.1 61.66,13.22 ; C25.1 61.11,12.64 ; C7.1 v1(37.52,26.32) ; 39.37,26.31 v1(40.46,26.31) ; C9.1 39.57,22.23
  L2_GND w0.635: P2.9 19.23,12.45 ; P2.9 19.23,14.22 ; P2.9 17.45,12.45 ; P2.9 17.45,14.22 ; 17.45,2.29 P2.1 ; P2.1 17.45,4.06 ; P2.1 19.23,2.29 ; P2.1 19.23,4.06 ; 14.91,7.37 P2.6 ; P2.6 16.69,9.14 ; P2.6 16.69,7.37 ; P2.6 14.91,9.14 ; 14.91,17.53 P2.14 ; P2.14 16.69,19.3 ; P2.14 16.69,17.53 ; P2.14 14.91,19.3 ; 17.45,32.77 P2.25 ; P2.25 17.45,34.54 ; P2.25 19.23,32.77 ; P2.25 19.23,34.54 ; P7.2 54.63,21.34 ; P7.2 54.63,23.11 ; P7.2 52.85,21.34 ; P7.2 52.85,23.11 ; 17.45,39.62 P2.29 ; P2.29 17.45,37.85 ; P2.29 19.23,37.85 ; P2.29 19.23,39.62 ; 14.91,22.61 P2.18 ; P2.18 16.69,22.61 ; P2.18 14.91,24.38 ; P2.18 16.69,24.38 ; 14.91,14.22 P2.10 ; P2.10 16.69,14.22 ; P2.10 16.69,12.45 ; P2.10 14.91,12.45 ; 17.45,7.37 P2.5 ; P2.5 19.23,7.37 ; P2.5 17.45,9.14 ; P2.5 19.23,9.14 ; P2.13 19.23,17.53 ; P2.13 17.45,19.3 ; P2.13 19.23,19.3 ; P2.13 17.45,17.53 ; 17.45,29.46 P2.21 ; P2.21 17.45,27.69 ; P2.21 19.23,27.69 ; P2.21 19.23,29.46 ; 14.91,27.69 P2.22 ; P2.22 16.69,27.69 ; P2.22 16.69,29.46 ; P2.22 14.91,29.46 ; 14.91,37.85 P2.30 ; P2.30 16.69,37.85 ; P2.30 14.91,39.62 ; P2.30 16.69,39.62 ; P2.17 19.23,22.61 ; P2.17 19.23,24.38 ; P2.17 17.45,24.38 ; P2.17 17.45,22.61 ; 14.91,4.06 P2.2 ; P2.2 16.69,2.29 ; P2.2 14.91,2.29 ; P2.2 16.69,4.06 ; P2.26 16.69,32.77 ; P2.26 14.91,34.54 ; P2.26 16.69,34.54 ; P2.26 14.91,32.77
  BOTTOM w0.203: P1.74 v1(3.87,29.53) ; P1.41 v1(7.47,19.37) ; P1.17 v1(7.47,11.75) ; P1.65 v1(9.98,26.99) ; P1.13 v1(9.98,10.48) ; P1.45 v1(7.47,20.64) ; 23.95,17.71 24.19,17.71 24.3,17.82 24.3,17.92 v1(24.19,17.92) ; P1.10 v1(3.87,9.21) ; P1.2 v1(3.87,6.67) ; P1.21 v1(9.98,13.02) ; P1.6 v1(6.38,7.94) ; P1.30 v1(6.38,15.56) ; 27.08,36.81 27.08,36.8 v1(27.06,36.8) ; P1.77 v1(7.47,30.8) ; P1.78 v1(6.38,30.8) ; P1.58 v1(3.87,24.45) ; P1.34 v1(3.87,16.83) ; P1.93 v1(7.47,35.88) ; P1.94 v1(6.38,35.88) ; P1.26 v1(3.87,14.29) ; P1.69 v1(7.47,28.26) ; P1.1 v1(9.98,6.67) ; P1.37 v1(9.98,18.1) ; P1.25 v1(7.47,14.29) ; P1.92 v1(3.87,35.24) ; P1.9 v1(7.47,9.21) ; P1.81 v1(9.98,32.07) ; P1.14 v1(6.38,10.48) ; P1.53 v1(7.47,23.18) ; P1.91 v1(9.98,35.24) ; P1.5 v1(7.47,7.94) ; P1.54 v1(6.38,23.18) ; P1.46 v1(6.38,20.64) ; P1.29 v1(9.98,15.56) ; P1.73 v1(9.98,29.53) ; P1.90 v1(6.38,34.61) ; P1.61 v1(7.47,25.72) ; P1.82 v1(3.87,32.07) ; P1.70 v1(6.38,28.26) ; P1.50 v1(3.87,21.91) ; P1.22 v1(6.38,13.02) ; P1.42 v1(3.87,19.37) ; P1.62 v1(6.38,25.72) ; P1.18 v1(3.87,11.75) ; P1.33 v1(7.47,16.83) ; P1.85 v1(9.98,33.34) ; P1.49 v1(7.47,21.91) ; P1.57 v1(7.47,24.45) ; P1.66 v1(3.87,26.99) ; P1.38 v1(6.38,18.1) ; P1.89 v1(7.47,34.61)
  BOTTOM w0.508: C48.2 v1(37.59,39.47) ; R30.1 v1(23.81,28.89) ; v1(21.8,28.89) 21.8,28.21 R28.1 ; R32.1 v1(25.91,28.89)
  BOTTOM w0.635: 19.23,14.22 P2.9 17.45,12.45 ; 25.46,23.42 U2.4 ; U2.4 v1(26.23,24.77) ; U2.4 25.46,26.11 ; 52.85,21.34 P7.2 ; P7.2 52.85,23.11 ; P7.2 54.63,23.11 ; P7.2 54.63,21.34 ; 16.69,12.45 P2.10 14.91,12.45 ; v1(50.72,8.76) C16.1 v1(50.72,11.63) ; C42.1 24.59,36.76 ; C42.1 22.48,36.76 ; C42.1 v1(23.54,35.66) ; 17.16,1.99 P2.1 19.52,1.99 ; 45.33,30.27 C49.N ; C49.N 43.86,32.2 ; C49.N 45.33,34.13 ; C49.N 46.8,32.2 ; 19.23,22.61 P2.17 17.45,22.61 ; 16.69,22.61 P2.18 14.91,22.61 ; C44.1 27.08,36.81 ; C5.1 39.57,21.72 ; C5.1 40.29,20.97 ; C5.1 39.57,20.23 ; v1(50.72,35.7) C29.1 v1(50.72,32.79) ; C41.1 v1(21.17,35.66) ; 40.15,25 C4.1 40.15,22.89 ; 14.91,39.62 P2.30 14.91,37.85 ; R33.1 v1(27.01,37.84) ; 19.23,9.14 P2.5 19.23,7.37 ; 16.69,17.53 P2.14 14.91,17.53 ; 14.91,2.29 P2.2 ; P2.2 16.69,2.29 ; P2.2 14.91,4.06 ; 23.4,18.3 C46.2 23.95,17.71 ; R34.1 v1(39.08,28.74) ; 14.91,27.69 P2.22 16.69,27.69 ; U2.7 v1(22.92,21.23)
  vias: v1(2.02,40.52) v1(2.02,37.98) v1(2.02,34.81) v1(2.02,31.63) v1(2.02,28.46) v1(2.02,25.92) v1(2.02,23.38) v1(2.02,20.84) v1(2.02,18.3) v1(2.02,15.76) v1(2.02,13.22) v1(2.02,10.68) v1(2.02,8.14) v1(2.02,5.6) v1(3.29,4.96) v1(3.92,43.06) v1(5.83,40.52) v1(5.83,2.42) v1(8.37,43.06) v1(8.37,4.96) v1(10.91,40.52) v1(10.91,2.42) v1(13.45,43.06) v1(13.45,40.52) v1(19.8,43.57) v1(21.45,43.57) v1(23.1,43.57) v1(24.75,43.57) v1(26.4,43.57) v1(28.05,43.57) v1(29.96,43.57) v1(31.86,43.57) v1(31.84,41.02) v1(32.37,39.97) v1(32.37,38.92) v1(32.37,37.88) v1(32.39,22.24) v1(32.39,20.87) v1(32.67,41.01) v1(33.31,39.99) v1(33.31,38.92) v1(33.31,37.88) v1(33.53,43.57) v1(33.51,42.43) v1(33.74,20.87) v1(35.16,43.57) v1(35.14,23.63) v1(35.11,22.21) v1(35.14,20.84) v1(36.94,43.57) v1(38.59,43.57) v1(39.82,22.49) v1(40.24,43.57) v1(40.56,21.96) v1(40.77,23.96) v1(41.09,22.49) v1(41.09,20.49) v1(41.8,33.6) v1(41.8,32.33) v1(41.8,31.06) v1(41.8,29.79) v1(41.8,28.52) v1(41.8,25.98) v1(41.8,24.71) v1(41.83,21.91) v1(41.8,19.43) v1(41.8,18.16) v1(41.8,16.89) v1(41.8,15.62) v1(41.8,14.35) v1(41.8,13.08) v1(41.8,11.81) v1(41.89,43.57) v1(41.89,10.55) v1(42.34,22.74) v1(42.7,9.57) v1(42.89,21.22) v1(43.16,23.71) v1(43.28,32.59) v1(43.28,31.32) v1(43.28,30.05) v1(43.28,28.78) v1(43.28,26.24) v1(43.28,24.97) v1(43.28,20.01) v1(43.28,18.74) v1(43.28,17.47) v1(43.28,16.2) v1(43.28,14.93) v1(43.28,13.66) v1(43.28,12.39) v1(43.28,11.12) v1(43.94,29.87) v1(43.97,28.88) v1(43.96,9.42) v1(45.2,23.38) v1(45.2,18.3) v1(45.36,29.87) v1(45.39,28.83) v1(46.79,29.82) v1(46.79,28.78) v1(47.74,25.92) v1(47.74,20.84) v1(47.74,15.76) v1(49.64,43.06) v1(50.28,28.46) v1(50.28,23.38) v1(50.28,18.3) v1(50.28,13.22) v1(52.18,40.52) v1(52.31,36.53) v1(52.31,31.71) v1(52.31,12.37) v1(52.31,7.97) v1(52.82,25.92) v1(52.82,20.84) v1(52.82,15.76) v1(54.72,43.06) v1(55.36,28.46) v1(55.36,18.3) v1(55.45,38.09) v1(55.45,30.47) v1(55.39,14.01) v1(55.4,6.31) v1(56.63,25.92) v1(56.63,20.84) v1(56.63,15.76) v1(57.26,40.52) v1(59.17,18.3) v1(59.8,43.06) v1(61.07,40.52) v1(61.65,35.9) v1(61.64,32.6) v1(61.65,11.85) v1(61.64,8.48) v1(61.71,15.76) v1(61.71,4.96) v1(61.71,2.42) v1(64.25,4.96) v1(64.25,2.42) v1(64.88,43.06) v1(64.88,40.52) v1(64.88,18.3) v1(66.79,4.96) v1(66.79,2.42) v1(67.21,40.41) v1(69.33,4.96) v1(69.33,2.42) v1(69.96,43.06) v1(71.87,25.92) v1(71.87,22.11) v1(71.87,18.3) v1(72.5,43.06) v1(72.5,40.52) v1(74.41,27.82) v1(74.41,24.01) v1(74.41,20.2) v1(74.41,16.39)
VBAT_IN: length 13.6
  L3_PWR w0.635: 14.91,40.39 P2.32 ; P2.32 16.69,42.16 ; P2.32 16.69,40.39 ; P2.32 14.91,42.16
  BOTTOM w0.203: P1.96 v1(3.87,36.51) ; P1.98 v1(6.38,37.15) ; P1.100 v1(3.87,37.78)
  BOTTOM w0.635: 20.52,40.69 E1.1 ; E1.1 21.38,41.67 ; E1.1 21.38,39.72 ; 20.12,38.67 C41.2 21.17,39.57
  vias: v1(19.63,42.47) v1(20.35,42.47) v1(21.06,42.47) v1(21.77,42.51)
VSSN: length 47.7
  TOP w0.305: v1(64.17,37.67) L14.1 62.73,36.76 62.66,36.69 ; 62.66,36.69 C39.2 ; 62.66,36.69 62.66,37.75 62.66,37.75 D4.C ; v1(35.31,25.55) 34.99,25.23 U1.26
  BOTTOM w0.203: v1(35.31,25.55) 37.18,27.42 63.45,27.42 63.86,27.82 64.38,27.82 64.95,28.4 64.95,33.93 64.33,34.55 C40.1 v1(64.17,37.67)
A2B_VBUS: length 27.5
  L3_PWR w0.635: 14.91,25.15 P2.20 ; P2.20 16.69,25.15 ; P2.20 16.69,26.92 ; P2.20 14.91,26.92 ; 30.54,34.67 P5.1 ; P5.1 32.31,34.67 ; P5.1 30.54,32.9 ; P5.1 32.31,32.9 ; P8.2 48.76,41.49 ; P8.2 46.98,39.72 ; P8.2 46.98,41.49 ; P8.2 48.76,39.72 ; 63.29,21.34 P6.1 ; P6.1 63.29,23.11 ; P6.1 65.06,21.34 ; P6.1 65.06,23.11
  BOTTOM w0.203: P1.95 v1(9.98,36.51) ; P5.1 31.43,32.13 D2.A D1.A ; P1.99 v1(9.98,37.78) ; P1.97 v1(7.47,37.15)
ACM: length 3.3
  TOP w0.305: C12.2 C8.2 36.92,20.47 U1.17
ADR1/IO1: length 44
  TOP w0.203: U1.7 30.8,20.98 30.28,20.45 30.28,19.25 29.62,18.59 v1(27.38,18.59) 23.49,18.59 22.04,17.14 17.07,17.14 P2.12 13.51,15.88 12.5,16.89 12.5,20.03 v1(9.98,22.54)
  TOP w0.305: v1(31.95,8.84) R4.2 R3.1
  L3_PWR w0.203: v1(31.95,8.84) 30.86,8.84 29.29,10.41 29.29,12.47 27.38,14.37 v1(27.38,18.59)
  BOTTOM w0.203: P1.51 v1(9.98,22.54)
ADR2/IO2: length 43.7
  TOP w0.203: U1.8 30.99,20.47 30.73,20.22 30.73,18.75 30.02,18.03 v1(25.1,18.03) 21.67,14.61 17.37,14.61 17.12,14.35 17.12,12.11 P2.8 13.28,10.79 11.94,12.14 11.94,19.32 v1(9.98,21.27)
  L3_PWR w0.203: P4.2 25.1,11.84 v1(25.1,18.03)
  BOTTOM w0.203: P1.47 v1(9.98,21.27)
AN: length 24.2
  TOP w0.114: U1.18 36.9,20.98 37.03,21.1 41.4,21.1 arc(42.12,20.81) 42.42,20.09 42.42,11.12 arc(42.51,10.66) 42.77,10.26 arc(43.02,10.1) 43.31,10.04 44.5,10.04 C17.1 45.26,10.03 47.05,10.03 L2.1 47.79,9.53 48.31,10.06 48.41,10.06 48.83,10.06 L4.1
AP: length 24.1
  TOP w0.114: L3.1 48.89,10.31 48.29,10.31 47.82,10.78 L1.2 47.29,10.78 46.79,10.29 45.26,10.29 C17.2 44.5,10.28 43.31,10.28 arc(43.11,10.32) 42.94,10.43 arc(42.73,10.75) 42.66,11.12 42.66,20.09 arc(42.29,20.98) 41.4,21.35 37.03,21.35 36.9,21.47 U1.19
BCM: length 3.3
  TOP w0.305: C11.2 C7.2 36.92,23.98 U1.24
BLCK: length 28.4
  TOP w0.305: R6.1 v1(29.95,13.67)
  BOTTOM w0.203: v1(29.95,13.67) 22.43,13.67 19.94,11.18 19.94,7.11 18.54,5.71 P2.3 17.07,6.98 11.43,6.98 11.11,7.3 P1.3
BN: length 24.2
  TOP w0.114: U1.23 36.9,23.47 37.03,23.35 41.4,23.35 arc(42.12,23.64) 42.42,24.36 42.42,33.59 arc(42.44,33.74) 42.49,33.88 arc(42.59,34.03) 42.71,34.16 arc(42.99,34.35) 43.31,34.41 44.5,34.41 C30.1 45.26,34.42 46.86,34.42 47.37,34.93 L9.1 47.75,34.93 48.27,34.4 48.85,34.4 L11.1
BP: length 24.2
  TOP w0.114: L10.1 48.87,34.16 48.26,34.16 47.76,33.66 L8.2 47.37,33.66 46.86,34.16 45.34,34.16 44.97,33.79 C30.2 44.5,34.17 43.31,34.17 arc(43.08,34.12) 42.88,33.99 arc(42.79,33.88) 42.7,33.76 arc(42.67,33.68) 42.66,33.59 42.66,33.6 42.66,24.36 arc(42.29,23.47) 41.4,23.1 37.03,23.1 36.9,22.98 U1.22
DRX0: length 49.5
  TOP w0.305: R10.1 v1(36.05,13.67)
  BOTTOM w0.203: v1(36.05,13.67) 33.46,16.26 20.83,16.26 20.19,16.89 20.19,24.18 P2.19 17.07,24.77 13.72,24.77 12.7,23.75 12.7,13.08 12,12.38 P1.19
DRX1: length 59.4
  TOP w0.305: R11.1 v1(37.57,13.67)
  BOTTOM w0.203: P1.23 11.24,13.65 11.94,14.35 11.94,29.08 12.7,29.84 17.07,29.84 P2.23 19.56,29.9 19.56,25.78 20.83,24.51 20.83,17.4 21.34,16.89 34.35,16.89 v1(37.57,13.67)
DTX0: length 30
  TOP w0.305: R8.1 v1(33,13.67)
  BOTTOM w0.203: P1.11 12.89,9.84 14.1,11.05 14.1,13.59 15.11,14.61 17.07,14.61 P2.11 19.23,14.99 31.68,14.99 v1(33,13.67)
DTX1: length 39.8
  TOP w0.305: R9.1 v1(34.52,13.67)
  BOTTOM w0.203: v1(34.52,13.67) 34.52,13.74 32.64,15.62 20.32,15.62 19.56,16.38 19.56,19.74 P2.15 17.07,19.69 14.05,19.69 13.46,19.1 13.46,12.19 12.38,11.11 P1.15
IO7: length 60.1
  TOP w0.203: v1(9.98,20) 9.98,19.99 11.35,18.62 11.35,6.81 12.45,5.71 P2.4 ; v1(40,9.62) 40,15.52 38.56,16.97 37.62,16.97 35.49,19.09 U1.16
  TOP w0.305: R1.2 v1(40,9.62)
  BOTTOM w0.203: P2.4 16.99,4.52 20.42,4.52 25.52,9.62 v1(40,9.62) ; P1.43 v1(9.98,20)
IOVDD: length 16.5
  TOP w0.203: v1(31.67,19.15) 31.99,19.47 U1.9
  TOP w0.305: v1(32.78,11.57) R3.2 R12.2
  BOTTOM w0.508: R29.2 v1(22.76,28.89) ; R27.2 20.66,28.59 v1(20.95,28.89) ; 24.65,29.09 24.86,28.89 R31.2
  BOTTOM w0.635: v1(28.96,19.71) R39.2 ; R39.2 29.58,20.72 ; R39.2 28.33,20.72 ; R40.2 29.58,23.67 ; R40.2 28.96,24.24 ; R40.2 28.33,23.67 ; C46.1 22.08,17.71 v1(21.65,18.14) U2.8
  BOTTOM w0.762: 24.65,29.09 P3.2
  vias: v1(26.16,21.54) v1(26.18,22.83) v1(29.98,23.51)
IRQ: length 38.3
  TOP w0.203: U1.6 30.62,21.47 29.84,20.7 29.84,19.71 29.28,19.15 v1(26.23,19.15) 22.12,19.15 21.62,19.66 17.1,19.66 P2.16 12.75,20.95 9.98,23.72 v1(9.98,25.08)
  TOP w0.305: R2.2 v1(26.24,10.31)
  L3_PWR w0.203: v1(26.24,10.31) 26.23,10.32 v1(26.23,19.15)
  BOTTOM w0.203: P1.59 v1(9.98,25.08)
SCL: length 36
  TOP w0.203: U1.4 30.01,22.47 v1(29.78,22.7) R14.1 28.7,22.86 28.07,23.49 23.74,23.49 20.4,26.84 20.4,35.2 19.41,36.2 P2.27
  BOTTOM w0.203: P2.27 16.94,34.8 13.46,34.8 12.64,33.97 P1.87 ; R38.2 R40.1 28.99,22.7 v1(29.78,22.7)
SDA: length 56
  TOP w0.203: P2.31 17.09,40.03 17.09,35.31 17.53,34.87 18.97,34.87 19.47,34.38 19.47,26.27 24.84,20.9 28.12,20.9 28.7,21.49 R15.1 v1(29.78,21.65) 30.11,21.98 U1.5
  BOTTOM w0.203: P1.83 12.76,32.7 13.08,32.38 19.18,32.38 19.69,32.89 19.69,36.7 19,37.39 17.56,37.39 17.07,37.88 17.07,40 P2.31 ; R37.2 28.06,21.72 R39.1 29.03,21.65 v1(29.78,21.65)
SENSE: length 47.7
  TOP w0.305: C14.2 37,31.88 ; 37,31.88 36.97,31.85 35.73,31.85 v1(35.71,31.87) Q1.3 ; 37,31.88 R19.2 ; C38.2 L13.2 v1(64.17,30.89)
  BOTTOM w0.203: v1(35.71,31.87) 35.71,28.61 36.49,27.82 63.28,27.82 64.17,28.72 v1(64.17,30.89) C40.2
SYNC: length 26.3
  TOP w0.305: R7.1 v1(31.47,13.67)
  BOTTOM w0.203: P1.7 13.4,8.57 14.35,9.53 17.07,9.53 P2.7 21.9,14.35 30.79,14.35 v1(31.47,13.67)
UNNAMED_2_AD242XV2_I1_ATRXVDD: length 8.3
  BOTTOM w0.635: 37.35,23.95 C4.2 ; C4.2 38.25,22.89 ; C4.2 38.25,25 ; R17.2 37.2,23.98 ; R17.2 36.42,22.85 ; R17.2 36.42,25.11 ; C5.2 37.97,21.72 ; C5.2 37.25,20.97 ; C5.2 37.97,20.23
  vias: v1(37.06,22.25)
UNNAMED_2_AD242XV2_I1_BCLK: length 4.6
  TOP w0.203: R6.2 32.49,18.76 U1.10
UNNAMED_2_AD242XV2_I1_DRX0: length 4.2
  TOP w0.203: R10.2 36.05,17.04 34.49,18.59 U1.14
UNNAMED_2_AD242XV2_I1_DRX1: length 4.6
  TOP w0.203: R11.2 34.99,18.79 U1.15
UNNAMED_2_AD242XV2_I1_DTX0: length 3.8
  TOP w0.203: R8.2 33,17.63 33.49,18.13 U1.12
UNNAMED_2_AD242XV2_I1_DTX1: length 3.8
  TOP w0.203: U1.13 33.99,18.08 34.52,17.55 R9.2
UNNAMED_2_AD242XV2_I1_SENSE: length 6.7
  TOP w0.203: R19.1 37,28.16 35.51,26.67 34.67,26.67 33.99,25.99 U1.28
UNNAMED_2_AD242XV2_I1_SWP: length 6.9
  TOP w0.203: R18.1 38.05,28.5 35.79,26.24 34.87,26.24 34.49,25.86 U1.27
UNNAMED_2_AD242XV2_I1_SYNC: length 4.2
  TOP w0.203: U1.11 32.99,18.52 31.47,17 R7.2
UNNAMED_2_AD242XV2_I1_VIN: length 7.4
  TOP w0.203: U1.30 32.99,25.43 v1(32.64,25.78) 32.39,26.03 C6.2
  TOP w0.635: C6.2 33.5,27.12 C10.2
  BOTTOM w0.203: v1(32.64,25.78) 31.62,26.8 D1.C
UNNAMED_2_CAP_I30_N1: length 6.3
  TOP w0.305: R18.2 38.05,31.33 C14.1 38.68,31.96 C13.1 38.7,33.33 R20.1 38.7,35.77 38.22,36.25 Q1.1
UNNAMED_2_CAP_I34_N2: length 13
  TOP w0.203: C13.2 v1(39.68,32.28)
  TOP w0.305: R20.2 40.63,34.33 C15.2 ; R20.2 39.7,33.33 C13.2 ; R20.2 39.7,35.42 R21.2
  L3_PWR w0.203: v1(39.68,32.28) 38.17,33.78 P5.2
  BOTTOM w0.203: D2.C 33.97,32 P5.2
UNNAMED_2_CN3P_I84_N1: length 3.7
  TOP w0.305: P4.1 28.32,10.79 R12.1
UNNAMED_2_CN3P_I84_N3: length 10.7
  TOP w0.305: R13.2 v1(28.92,9.06)
  L3_PWR w0.203: P4.3 24.98,9.06 v1(28.92,9.06)
UNNAMED_2_DIOLED_I85_P: length 2.8
  TOP w0.305: DS1.A R1.1
UNNAMED_2_DIOLED_I86_P: length 2.8
  TOP w0.305: R2.1 DS2.A
UNNAMED_2_DIOLED_I87_P: length 6.1
  TOP w0.305: R4.1 DS3.A 31.96,4.99 30.98,5.97 R5.2
UNNAMED_2_RES_I39_N1: length 2.3
  TOP w0.305: Q1.2 39.85,38.17 R21.1
UNNAMED_3_CAP_I3_N2: length 7.2
  TOP w0.305: L2.2 v1(48.7,7.73) ; L1.1 v1(48.7,12.59)
  BOTTOM w0.203: v1(48.7,12.59) 48.7,10.28 C16.2 48.7,10.04 v1(48.7,7.73)
UNNAMED_3_CAP_I10_N2: length 4.4
  TOP w0.114: L5.2 53.49,9.66 53.1,10.05 52.63,10.05 C19.2 51.98,10.04 51.7,10.04 C20.1 50.92,10.04 50.58,10.04 L4.2
UNNAMED_3_CAP_I12_N2: length 4.4
  TOP w0.114: L3.2 50.56,10.29 50.94,10.29 C20.2 51.68,10.29 51.97,10.29 C18.1 52.64,10.29 53.11,10.29 53.49,10.66 L5.1
UNNAMED_3_CAP_I20_N1: length 5.9
  TOP w0.114: L5.3 56.92,9.66 57.3,10.03 58.06,10.03 58.91,9.18 R23.1 59.98,9.18 60.83,10.03 61.29,10.03 C24.1
UNNAMED_3_CAP_I20_N2: length 5.8
  TOP w0.114: P9.2 66.25,9.16 65.36,10.05 64.91,10.05 64.36,9.5 L7.2 63.98,9.5 63.44,10.04 63.03,10.04 C24.2
UNNAMED_3_CAP_I22_N1: length 6
  TOP w0.114: L5.4 56.91,10.66 57.3,10.27 58.01,10.27 58.9,11.15 R22.2 59.95,11.15 60.83,10.27 61.27,10.27 C23.1
UNNAMED_3_CAP_I22_N2: length 5.8
  TOP w0.114: P9.1 66.23,11.16 65.36,10.29 64.91,10.29 64.37,10.83 L6.1 64,10.83 63.45,10.28 63.04,10.28 C23.2
UNNAMED_3_CAP_I24_N2: length 23.9
  TOP w0.305: P7.1 56.34,22.29 C28.1 60.74,22.29 R24.1 v1(61.29,19.99) ; v1(64.17,6.78) L7.1 C26.2
  BOTTOM w0.203: v1(61.29,19.99) 63.09,18.19 63.09,10.69 64.12,9.66 C27.1 v1(64.17,6.78)
UNNAMED_3_CAP_I25_N2: length 15
  TOP w0.305: C25.2 L6.2 v1(64.17,13.55)
  BOTTOM w0.203: P6.2 66.71,16.09 v1(64.17,13.55) C27.2
UNNAMED_3_CAP_I29_N2: length 17
  TOP w0.203: v1(59.42,5.14) R23.2 59.4,6.36 C22.2 ; C21.1 59.4,13.98 R22.1 v1(59.43,15.19)
  BOTTOM w0.203: v1(59.42,5.14) 59.43,5.15 v1(59.43,15.19)
UNNAMED_3_CAP_I35_N2: length 5.2
  TOP w0.305: C28.2 60.74,24.19 R24.2 63.86,24.74 D3.C
UNNAMED_3_CN3P_I36_N3: length 5.5
  TOP w0.305: D3.A 68.56,24.76 69.25,24.07 P6.3
UNNAMED_4_CAP_I5_N1: length 6
  TOP w0.114: C36.1 61.28,34.17 60.88,34.17 59.98,33.27 R25.2 58.87,33.27 57.96,34.18 57.34,34.18 56.95,33.79 L12.3
UNNAMED_4_CAP_I5_N2: length 5.8
  TOP w0.114: C36.2 63.04,34.17 63.42,34.17 63.98,33.61 L13.1 64.4,33.61 64.96,34.17 65.38,34.17 66.27,33.29 P10.2
UNNAMED_4_CAP_I9_N1: length 5.9
  TOP w0.114: C37.1 61.28,34.41 60.87,34.41 59.99,35.29 R26.1 58.87,35.29 58,34.42 57.33,34.42 56.96,34.79 L12.4
UNNAMED_4_CAP_I9_N2: length 5.8
  TOP w0.114: C37.2 63.04,34.41 63.41,34.41 63.95,34.95 L14.2 64.42,34.95 64.95,34.41 65.37,34.41 66.25,35.29 P10.1
UNNAMED_4_CAP_I12_N1: length 4.4
  TOP w0.114: L12.1 53.54,34.79 53.16,34.41 52.64,34.41 C32.2 51.97,34.41 51.69,34.41 C33.1 50.93,34.41 50.58,34.41 L11.2
UNNAMED_4_CAP_I12_N2: length 4.4
  TOP w0.114: L12.2 53.54,33.79 53.16,34.17 52.63,34.17 C31.1 51.98,34.16 51.68,34.16 C33.2 50.93,34.17 50.58,34.17 L10.2
UNNAMED_4_IND_I17_N1: length 7.3
  TOP w0.305: L9.2 v1(48.71,36.73) ; L8.1 v1(48.71,31.85)
  BOTTOM w0.203: v1(48.71,36.73) 48.71,34.16 C29.2 48.71,33.94 v1(48.71,31.85)
UNNAMED_4_RES_I10_N1: length 17
  TOP w0.305: v1(59.43,39.33) R26.2 57.21,38.08 C34.1 ; C35.2 57.21,30.48 R25.1 v1(59.43,29.24)
  BOTTOM w0.203: v1(59.43,29.24) v1(59.43,39.33)
UNNAMED_5_CAP_I12_N2: length 2.2
  BOTTOM w0.203: C44.2 28.88,36.81 29.75,37.68 U3.2
UNNAMED_5_CAP_I13_N1: length 1.6
  BOTTOM w0.203: C48.1 36.59,38.68 U3.13
UNNAMED_5_CAP_I14_N1: length 2
  BOTTOM w0.203: C47.1 36.49,39.63 36.03,39.18 U3.12
UNNAMED_5_CAP_I23_N1: length 7.8
  BOTTOM w0.203: U3.16 34.99,35.44 36.42,34.01 R35.1 37.42,32.61 C45.1 37.42,31.14 R34.2
UNNAMED_5_CAP_I23_N2: length 12.1
  BOTTOM w0.203: U3.14 36.04,38.18 36.51,37.71 R36.1
  BOTTOM w0.635: R36.1 40.08,37.71 L16.2 39.34,36.31 39.42,36.23 R35.2 38.42,32.61 C45.2
UNNAMED_5_CAP_I42_N2: length 10.9
  BOTTOM w0.635: 24.89,40.74 L15.1 ; L15.1 25.88,41.87 25.44,42.32 24.18,42.32 24.14,42.28 ; L15.1 25.88,38.64 ; E1.2 23.07,41.67 ; E1.2 23.07,39.72 ; E1.2 23.93,40.69 ; 23.54,39.57 C42.2 24.59,38.67
UNNAMED_5_IC24XX512_I49_A0: length 3.4
  BOTTOM w0.203: U2.1 21.65,27.07 R28.2 R27.1
UNNAMED_5_IC24XX512_I49_A1: length 3.5
  BOTTOM w0.203: U2.2 22.92,26.95 R29.1 R30.2
UNNAMED_5_IC24XX512_I49_A2: length 3.7
  BOTTOM w0.203: R32.2 R31.1 24.64,26.9 24.64,26.03 24.19,25.59 U2.3
UNNAMED_5_IC24XX512_I49_SCL: length 5.1
  BOTTOM w0.203: U2.6 24.19,21.63 24.74,22.17 26.37,22.17 26.86,22.67 R38.1
UNNAMED_5_IC24XX512_I49_SDA: length 3.1
  BOTTOM w0.203: U2.5 25.46,20.5 25.67,20.7 26.67,20.7 26.96,20.99 R37.1
UNNAMED_5_LINLT8620_I8_PG: length 2.2
  BOTTOM w0.203: U3.15 35.8,37.68 36.08,37.4 36.08,37.27 36.64,36.71 R36.2
UNNAMED_5_LINLT8620_I8_RT: length 2
  BOTTOM w0.203: U3.3 29.13,38.18 R33.2
VOUT1: length 13.6
  TOP w0.635: P2.24 16.69,30.23 ; P2.24 14.91,30.23 ; P2.24 14.91,32 ; P2.24 16.69,32
  L3_PWR w0.635: P2.24 16.69,32 ; P2.24 16.69,30.23 ; P2.24 14.91,32 ; P2.24 14.91,30.23 ; 22.11,32.6 P3.1 20.93,33.78
  BOTTOM w0.203: P1.86 v1(6.38,33.34)
VOUT2: length 30.4
  TOP w0.305: v1(33.42,25.93) 33.49,25.85 U1.29
  TOP w0.635: 14.91,37.08 P2.28 14.91,35.31
  L3_PWR w0.635: P2.28 16.69,37.08 ; P2.28 14.91,35.31 ; P2.28 16.69,35.31 ; P2.28 14.91,37.08 ; P3.3 28.08,34.67 ; P3.3 26.31,32.9 ; P3.3 28.08,32.9 ; P3.3 26.31,34.67
  BOTTOM w0.203: P1.88 v1(3.87,33.97)
  BOTTOM w0.635: v1(33.42,25.93) 33.42,25.92 R17.1
  BOTTOM w0.762: R17.1 31.8,23.98 29.29,26.49 29.29,31.69 P3.3

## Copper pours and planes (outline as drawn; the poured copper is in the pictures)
DGND on TOP: 1.27,43.83 74.93,43.83 74.93,1.27 1.27,1.27 ; 15 cut-outs
DGND on BOTTOM: 1.27,43.83 74.93,43.83 74.93,1.27 1.27,1.27 ; 16 cut-outs
DGND on L2_GND: 1.27,43.83 74.93,43.83 74.93,1.27 1.27,1.27 ; 2 cut-outs
DGND on L3_PWR: 22.64,43.83 46.37,43.83 46.37,27.79 33.38,27.79 33.38,34.48 22.31,34.48 20.22,36.57 20.22,37.94 20.21,37.95 19.45,37.95 19.45,39.55 22.64,39.55 22.64,39.55
VBAT_IN on BOTTOM: 19.35,42.75 22.02,42.75 22.02,38.05 19.35,38.05
VBAT_IN on L3_PWR: 1.3,43.81 22.3,43.81 22.3,39.75 14.12,39.75 14.12,39.75 6.63,39.75 6.63,36.88 1.3,31.55
A2B_VBUS on L3_PWR: 46.55,43.79 74.93,43.79 74.93,1.27 7.44,1.27 1.35,1.27 1.35,31.34 6.94,36.94 6.94,38.85 13.35,38.85 13.35,27.41 17.27,27.41 17.27,26.03 17.32,26.03 17.32,8 37.01,8 37.01,24.32 29.9,24.32 29.9,35.12 32.89,35.12 32.89,27.66 32.93,27.61 46.56,27.61 46.56,35.12 46.55,35.12 ; 2 cut-outs
IOVDD on TOP: 25.86,22.93 25.86,21.47 26.05,21.29 27.91,21.29 27.91,23.09 26.02,23.09
IOVDD on BOTTOM: 20.29,29.66 20.29,28.62 25.1,28.62 25.1,30.36 20.99,30.36
IOVDD on BOTTOM: 28.04,24.61 28.04,18.64 31.93,18.64 31.93,19.41 31.34,20 31.34,23.3 30.03,24.61
IOVDD on L3_PWR: 22.84,31.25 29.22,31.25 29.22,23.92 36.47,23.92 36.47,10.34 31.96,10.34 31.96,15.82 27.45,20.33 23.87,20.33 22.42,18.88 22.42,17.69 18.16,17.69 18.16,26.57
UNNAMED_2_AD242XV2_I1_ATRXVDD on TOP: 35.94,22.61 35.94,21.84 37.97,21.84 37.97,22.61
UNNAMED_2_AD242XV2_I1_ATRXVDD on BOTTOM: 36.14,25.6 36.14,18.9 38.63,18.9 38.63,25.6
UNNAMED_2_AD242XV2_I1_DVDD1 on TOP: 31.55,22.86 31.55,24 29.46,26.09 29.46,30.78 27.56,30.78 27.56,28.83 28.07,28.32 28.07,26.16 28.32,25.91 28.32,24.51 28.45,24.38 28.45,23.75 29.84,23.75 30.73,22.86
UNNAMED_5_CAP_I9_N2 on BOTTOM: 27.66,42.81 27.66,38.91 29.57,38.91 29.95,38.53 31.39,38.53 31.39,39.83 29.57,39.83 29.31,40.08 29.31,41.35 29.62,41.66 31.24,41.66 31.24,42.81
UNNAMED_5_CAP_I14_N2 on BOTTOM: 38.58,39.34 42.29,39.34 42.29,42.48 42.08,42.68 34.47,42.68 34.47,39.52 35.69,39.52 36.5,40.34 37.59,40.34
UNNAMED_5_CAP_I23_N2 on BOTTOM: 44.07,41.73 46.56,41.73 46.56,35.76 46.53,35.76 46.53,35.71 38.58,35.71 38.58,38.02 44.07,38.02
UNNAMED_5_CAP_I42_N2 on BOTTOM: 22.5,42.79 22.5,38.02 26.62,38.02 26.62,42.79
VOUT1 on TOP: 5.31,34.29 8.13,34.29 8.13,32.82 17.3,32.82 17.3,29.62 5.31,29.62
VOUT1 on TOP: 21.29,34.62 22.94,34.62 22.94,32.77 31.62,32.77 31.62,25.53 32.13,25.02 32.13,24.26 31.88,24.26 30.15,25.98 30.15,31.22 21.29,31.22
VOUT1 on L3_PWR: 14.15,34.16 14.15,28.27 18.92,28.27 22.49,31.83 22.49,34.15 14.4,34.15 14.4,34.16
VOUT2 on TOP: 3.06,38.56 17.3,38.56 17.3,33.2 8.61,33.2 8.53,33.27 8.53,34.77 4.98,34.77 4.98,29.62 3.06,29.62
VOUT2 on L3_PWR: 14.43,37.73 19.98,37.73 19.98,36.33 25.59,36.33 25.59,35.15 29.39,35.15 29.39,32.28 22.95,32.28 22.95,34.55 14.43,34.55

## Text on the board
Ref Des/Silkscreen Top: A | C | ADZS-AD2428MINI | VBUS | POWER_EN | VOUT1 | IOVDD | VOUT2 | LOCAL
PAGE_OUTLINE: 27JUN19 | B | AS PER ECR-090225 | 17SEP19 | D.HARRINGTON
DIMENSION: REF | DIA MAX | -
User.15: NOTE: ALL IMPEDANCE TOLERANCE +/-10% | LAYER | L1 | 100 OHMS DP | IMPEDANCE | DP = DIFFERENTIAL PAIR | REFERENCE | L2 | LINE WIDTH | 4.5MILS | SPACE | 5MILS | IMPEDANCE TABLE
User.23: L2 GND | 08-      -07
User.24: L3 PWR | 08-      -08
User.45: FIGURE | SIZE | 10.0 | 45.0 | 35.0 | PLATED | NON-PLATED | FINISHED HOLES IN MILS | ALL UNITS ARE IN MILS | QTY | 295 | 47 | 2 | TOLERANCE/NOTES
